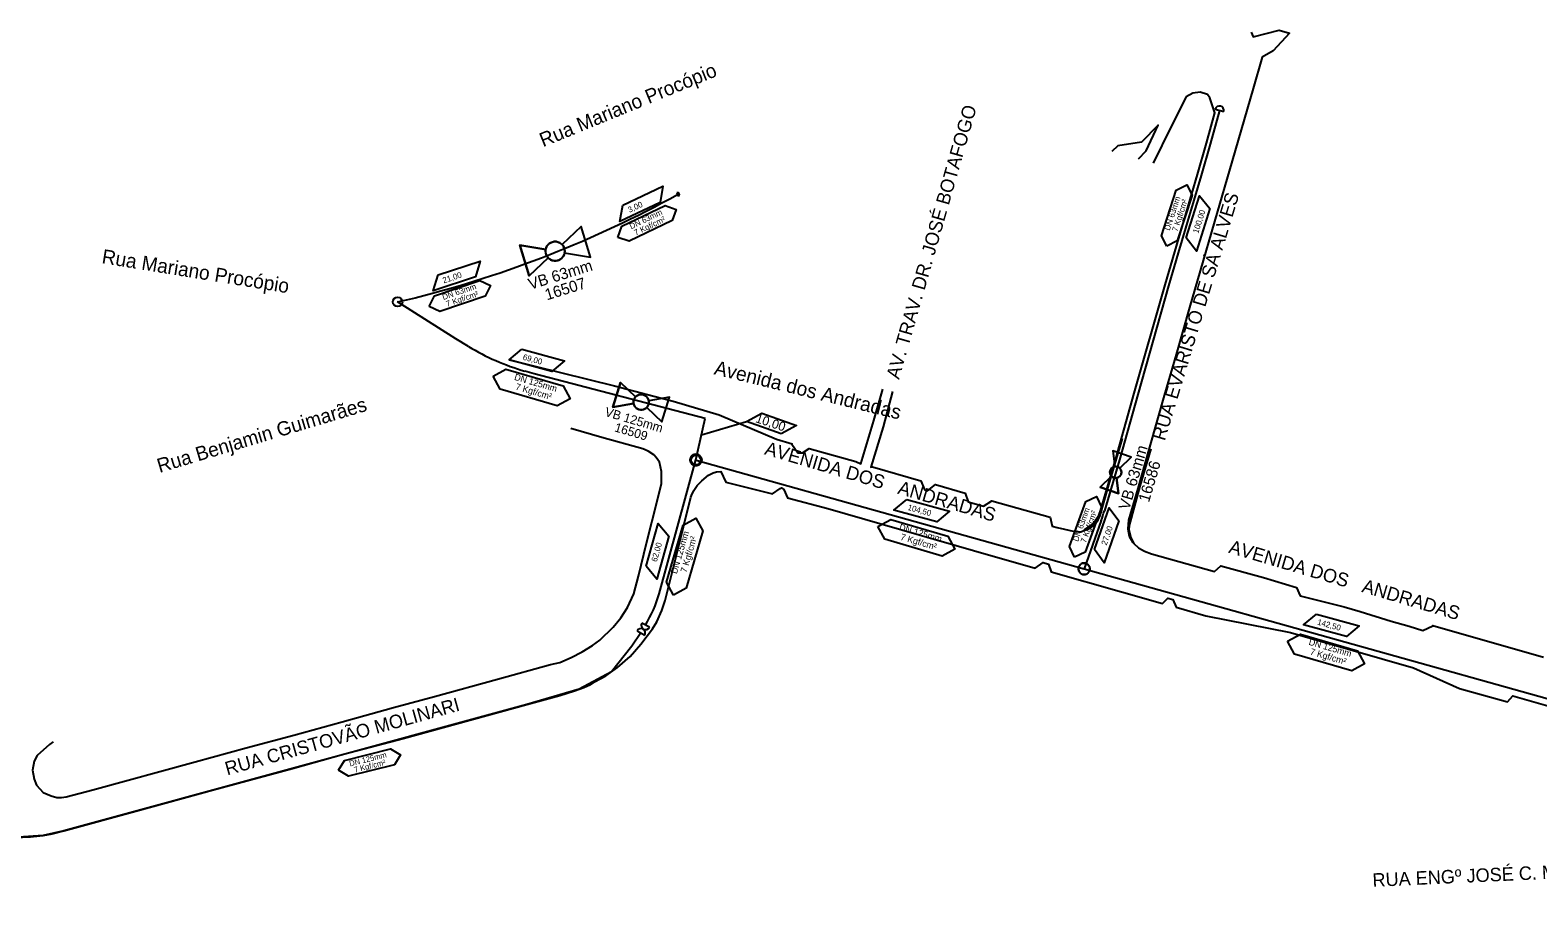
# Model space of a CAD drawing. Extents: x 656692 to 673945, y 7585994 to 7599066.
# Drawn here: x 667977 to 668779, y 7596748 to 7597212 of the extents above; entities that cross this region are included whole.
import ezdxf

# ---------------------------------------------------------------- set-up
doc = ezdxf.new("R2010")
doc.units = 0
for name, color, linetype in [('LEGENDA', 7, 'Continuous'), ('LOGRADOURO', 7, 'Continuous'), ('LOGRADOURO_TEXTO', 7, 'Continuous'), ('SIMBOLO', 7, 'Continuous'), ('TEXTO', 7, 'Continuous'), ('TEXTO NOME DE RUA', 7, 'Continuous'), ('TUBO_PEAD_GN_125', 7, 'Continuous'), ('TUBO_PEAD_GN_63', 7, 'Continuous'), ('VALVULA_PEAD_125', 7, 'Continuous'), ('VALVULA_PEAD_63', 7, 'Continuous')]:
    doc.layers.add(name, color=color, linetype=linetype)

# ---------------------------------------------------------------- blocks, each defined once
blk = doc.blocks.new('INTERLIGACAO_12')
at = {"layer": 'SIMBOLO'}
blk.add_circle((0, 0), 4.19, dxfattribs=at)
for start, end in [(0, 180), (180, 0)]:
    blk.add_arc((0, 0), 4.19, start, end, dxfattribs=at)
blk = doc.blocks.new('VALVULA_PEAD_DN_20')
at = {"layer": 'VALVULA_PEAD_63'}
for points in [[(-0.037, 0.019), (-0.14, 0.07), (-0.14, -0.07), (-0.037, -0.019)], [(-0.037, -0.019), (-0.14, -0.07), (-0.14, 0.07), (-0.037, 0.019)], [(0.037, -0.019), (0.14, -0.07), (0.14, 0.07), (0.037, 0.019)], [(0.037, -0.019), (0.14, -0.07), (0.14, 0.07), (0.037, 0.019)]]:
    blk.add_lwpolyline(points, dxfattribs=at)
blk.add_circle((0, 0), 0.0419, dxfattribs=at)
for start, end in [(90, 270), (153.4349, 206.5651), (270, 90), (333.4349, 26.5651)]:
    blk.add_arc((0, 0), 0.0419, start, end, dxfattribs=at)
blk = doc.blocks.new('VALVULA_PEAD_DN_9')
at = {"layer": 'VALVULA_PEAD_63'}
for points in [[(-1.14, 0.57), (-4.25, 2.13), (-4.25, -2.13), (-1.14, -0.57)], [(-1.14, -0.57), (-4.25, -2.13), (-4.25, 2.13), (-1.14, 0.57)], [(1.14, -0.57), (4.25, -2.13), (4.25, 2.13), (1.14, 0.57)], [(1.14, -0.57), (4.25, -2.13), (4.25, 2.13), (1.14, 0.57)]]:
    blk.add_lwpolyline(points, dxfattribs=at)
blk.add_circle((0, 0), 1.28, dxfattribs=at)
for start, end in [(90, 270), (153.4349, 206.5651), (270, 90), (0, 26.5651), (333.4349, 0)]:
    blk.add_arc((0, 0), 1.28, start, end, dxfattribs=at)

msp = doc.modelspace()

# ---------------------------------------------------------------- linework, layer by layer
at = {"layer": 'LEGENDA'}
for centre in [(668172.27, 7597067.58), (668172.27, 7597067.58), (668330.9, 7596983.47), (668330.9, 7596983.47)]:
    msp.add_circle(centre, 2.54, dxfattribs=at)
at = {"layer": 'LOGRADOURO'}
for points in [[(668626.08, 7597211.04), (668627.16, 7597208.64), (668640.96, 7597212.15), (668646.46, 7597210.47), (668637.9, 7597201.09), (668632.06, 7597197.78), (668627.21, 7597181.13), (668616.04, 7597142.63), (668606.69, 7597110.42), (668599.05, 7597084.04), (668593.36, 7597064.61), (668586.31, 7597039.61), (668579.97, 7597017.83), (668576.19, 7597004.62), (668571.76, 7596988.99), (668565.84, 7596968.34), (668560.92, 7596951.45), (668560.52, 7596946.77), (668561.35, 7596942.97), (668563.23, 7596939.55)], [(668537.37, 7596946.27), (668542.01, 7596949.23), (668545.45, 7596954.66), (668554.12, 7596984.06), (668563.99, 7597018.93), (668580.33, 7597076.63), (668585.47, 7597094.17), (668597.59, 7597135.42), (668602.35, 7597152.08), (668606.88, 7597168.2), (668604.21, 7597176.21), (668602.9, 7597177.91), (668598.97, 7597179.18), (668595.17, 7597178.64), (668591.6, 7597176.72), (668583.47, 7597160.51), (668573.97, 7597141.42)], [(668566.2, 7597143.64), (668570.23, 7597148.02), (668576.63, 7597161.67), (668567.87, 7597152.49), (668555.23, 7597150.54), (668552.01, 7597147.67)], [(668231.57, 7597036.76), (668287.62, 7597022.96), (668308.53, 7597017.47), (668318.87, 7597014.71), (668343.33, 7597007.51), (668373.67, 7596994.48), (668382.08, 7596992.01), (668381.89, 7596991.82), (668385.03, 7596987.27), (668387.5, 7596987.21), (668391.05, 7596989.56), (668415.9, 7596982.57), (668418.65, 7596981.34), (668425.47, 7597004.52), (668430.28, 7597021.14)], [(668435.45, 7597019.81), (668430.42, 7597001.01), (668423.99, 7596979.69), (668424.76, 7596979.82), (668450.43, 7596972.4), (668452.48, 7596967.81), (668454.09, 7596967.02), (668458.29, 7596970.36), (668474.03, 7596965.89), (668475.67, 7596961.26), (668483.8, 7596958.94), (668488.18, 7596961.75), (668519.21, 7596953.04), (668520.38, 7596948.3), (668522.97, 7596947.61), (668533.18, 7596945.22), (668535.98, 7596945.48), (668539.73, 7596946.86), (668541.44, 7596947.92), (668542.95, 7596949.2), (668544.84, 7596951.65), (668545.81, 7596953.84), (668550.46, 7596970.18), (668557.68, 7596994.91)], [(667989.12, 7596833.52), (667987.12, 7596832.04), (667980.56, 7596826.17), (667979.12, 7596823.3), (667978.23, 7596818.35), (667978.96, 7596813.58), (667980.3, 7596810.54), (667983.91, 7596806.5), (667988.03, 7596804.72), (667991.12, 7596803.9), (667993.61, 7596803.96), (667996.09, 7596804.3), (668010.31, 7596808.06), (668064.6, 7596822.88), (668091.83, 7596830.34), (668117.03, 7596837.13), (668142.76, 7596844.14), (668170.1, 7596851.74), (668191.97, 7596857.61), (668225.36, 7596866.83), (668253.67, 7596874.57), (668258.5, 7596875.77), (668264.58, 7596878.32), (668270.38, 7596881.48), (668275.85, 7596884.74), (668279.83, 7596887.57), (668286.87, 7596894.44), (668291.07, 7596899.43), (668294.53, 7596904.96), (668297.83, 7596912.33), (668300.42, 7596921.67), (668304.72, 7596939.27), (668310.45, 7596962.29), (668312.64, 7596970.93), (668312.62, 7596977.36), (668311.52, 7596982.25), (668309.76, 7596984.83), (668308.47, 7596986.17), (668305.49, 7596988.08), (668302.68, 7596989.33), (668280.96, 7596995.48), (668264.32, 7597000.28)], [(668572.76, 7596989.48), (668567.01, 7596969.51), (668561.22, 7596948.62), (668561.18, 7596946.18), (668562.19, 7596942.01), (668563.73, 7596939.1), (668566.25, 7596936.67), (668569.43, 7596934.93), (668573.14, 7596933.58), (668606.72, 7596924.12), (668610.05, 7596927.16), (668632.78, 7596921.02), (668650.19, 7596915.7), (668652.14, 7596911.14), (668675.68, 7596905.4), (668684.18, 7596902.92), (668700.57, 7596897.77), (668710.14, 7596895.03), (668717.43, 7596892.7), (668722.68, 7596895.27), (668722.66, 7596895.4), (668781.51, 7596878.51)], [(667964.45, 7596782.52), (667977.13, 7596783.01), (667983.77, 7596783.76), (667988.56, 7596784.6), (667994.84, 7596786.2), (668033.19, 7596796.69), (668074.33, 7596807.96), (668116.41, 7596819.36), (668143.54, 7596826.87), (668175.24, 7596835.33), (668240.99, 7596853.41), (668258.49, 7596858.21), (668266.4, 7596860.71), (668271.35, 7596862.5), (668274.43, 7596863.88), (668276.94, 7596865.35), (668282.96, 7596868.61), (668289.16, 7596872.98), (668295.86, 7596878.88), (668301.64, 7596885.47), (668307.84, 7596893.71), (668310.17, 7596897.41), (668312.76, 7596903.31), (668314.56, 7596908.7), (668320.49, 7596932.15), (668328.28, 7596963.75), (668328.88, 7596965.4), (668329.76, 7596967), (668329.88, 7596967.28), (668331.64, 7596969.95), (668334.06, 7596972.44), (668337.66, 7596975.35), (668340.05, 7596976.57), (668341.8, 7596977.13), (668344.08, 7596977.27), (668346.85, 7596971.74), (668371.62, 7596965.52), (668375.64, 7596968.25), (668376.45, 7596968.59), (668377.57, 7596967.73), (668379.52, 7596963.26), (668401.11, 7596957.66), (668478.52, 7596935.35), (668511.35, 7596925.92), (668515.55, 7596928.97), (668518.46, 7596927.96), (668519.85, 7596923.9), (668557.24, 7596913.32), (668578.93, 7596907.16), (668581.75, 7596910.03), (668584.49, 7596909.29), (668586.29, 7596905.23), (668601.97, 7596900.47), (668647.03, 7596891.63), (668712.39, 7596872.94), (668737, 7596861.85), (668762.42, 7596854.78), (668765.32, 7596857.97), (668788.84, 7596851.31)]]:
    msp.add_lwpolyline(points, dxfattribs=at)
at = {"layer": 'SIMBOLO'}
msp.add_line((668333.84, 7596996.9), (668357.79, 7597003.98), dxfattribs=at)
for points in [[(668581.23, 7597097.17), (668578.39, 7597102.74), (668586.28, 7597127.03), (668591.85, 7597129.87), (668594.69, 7597124.3), (668586.81, 7597100.01), (668581.23, 7597097.17)], [(668289.43, 7597101.87), (668291.5, 7597107.77), (668314.52, 7597118.84), (668320.42, 7597116.77), (668318.35, 7597110.87), (668295.34, 7597099.8), (668289.43, 7597101.87)], [(668189.12, 7597065.19), (668191.89, 7597070.8), (668216.07, 7597079), (668221.68, 7597076.23), (668218.91, 7597070.62), (668194.73, 7597062.42), (668189.12, 7597065.19)], [(668223.07, 7597027.99), (668229.87, 7597031.72), (668260.25, 7597022.83), (668263.97, 7597016.03), (668257.17, 7597012.3), (668226.79, 7597021.19), (668223.07, 7597027.99)], [(668532.29, 7596931.69), (668529.61, 7596937.35), (668538.22, 7596961.39), (668543.88, 7596964.07), (668546.55, 7596958.41), (668537.95, 7596934.37), (668532.29, 7596931.69)], [(668318.92, 7596911.62), (668315.2, 7596918.42), (668324.09, 7596948.79), (668330.89, 7596952.52), (668334.61, 7596945.71), (668325.72, 7596915.34), (668318.92, 7596911.62)], [(668427.7, 7596948.06), (668434.5, 7596951.78), (668464.87, 7596942.89), (668468.6, 7596936.09), (668461.8, 7596932.37), (668431.42, 7596941.25), (668427.7, 7596948.06)], [(668645.5, 7596887.03), (668652.3, 7596890.75), (668682.68, 7596881.86), (668686.4, 7596875.06), (668679.6, 7596871.34), (668649.22, 7596880.23), (668645.5, 7596887.03)], [(668140.91, 7596818.36), (668144.09, 7596823.66), (668168.59, 7596829.77), (668173.9, 7596826.59), (668170.71, 7596821.28), (668146.21, 7596815.17), (668140.91, 7596818.36)]]:
    msp.add_lwpolyline(points, dxfattribs=at)
msp.add_lwpolyline([(668376.25, 7596997.37), (668357.79, 7597003.98), (668365.87, 7597008.4), (668384.34, 7597001.79)], close=True, dxfattribs=at)
at = {"layer": 'TEXTO'}
for points in [[(668292.05, 7597119.11), (668313.33, 7597129.09), (668311.92, 7597120.44), (668290.51, 7597110.4), (668292.05, 7597119.11)], [(668591.63, 7597101.66), (668598.72, 7597124.07), (668604.13, 7597117.17), (668596.99, 7597094.62), (668591.63, 7597101.66)], [(668193.8, 7597081.99), (668216.14, 7597089.32), (668213.69, 7597080.91), (668191.22, 7597073.53), (668193.8, 7597081.99)], [(668238.4, 7597042.38), (668261.06, 7597036.14), (668254.37, 7597030.48), (668231.57, 7597036.76), (668238.4, 7597042.38)], [(668443.03, 7596962.44), (668465.69, 7596956.2), (668459, 7596950.54), (668436.2, 7596956.82), (668443.03, 7596962.44)], [(668542.82, 7596935.87), (668550.57, 7596958.06), (668555.77, 7596951), (668547.96, 7596928.68), (668542.82, 7596935.87)], [(668304.53, 7596926.95), (668310.77, 7596949.61), (668316.43, 7596942.92), (668310.16, 7596920.12), (668304.53, 7596926.95)], [(668660.83, 7596901.41), (668683.49, 7596895.18), (668676.8, 7596889.52), (668654, 7596895.79), (668660.83, 7596901.41)]]:
    msp.add_lwpolyline(points, dxfattribs=at)
at = {"layer": 'TUBO_PEAD_GN_125'}
for p, q in [((668330.9, 7596983.47), (668335.75, 7597005.62)), ((668331.12, 7596983.38), (668805.83, 7596850.22)), ((668306.21, 7596894.45), (668302.1, 7596896.67)), ((668299.63, 7596892.5), (668303.74, 7596890.28))]:
    msp.add_line(p, q, dxfattribs=at)
for points in [[(668209.95, 7597043.89), (668203.33, 7597047.89), (668172.27, 7597067.58)], [(668335.75, 7597005.62), (668244.84, 7597029.29), (668239.91, 7597030.73)], [(668311.42, 7596912.27), (668330.9, 7596983.47), (668330.9, 7596983.47)], [(668301.62, 7596891.42), (668296.79, 7596884.36), (668286.06, 7596870.79), (668268.87, 7596861.6), (668240.99, 7596853.41), (667994.84, 7596786.2), (667983.77, 7596783.76), (667970.79, 7596782.76), (667952.83, 7596783.61), (667909.51, 7596794.38), (667905.28, 7596794.54), (667902.59, 7596794.01), (667893.41, 7596789.27), (667867.11, 7596772.34), (667851.19, 7596757.31), (667844.21, 7596747.84), (667786.16, 7596779.27)]]:
    msp.add_lwpolyline(points, dxfattribs=at)
for centre, radius, start, end in [((668275.16, 7597151.7), 126, 238.82978, 253.75404), ((668240.45, 7596933.53), 74.09, 329.20041, 343.32059), ((668304.16, 7596895.56), 2.34, 151.64019, 331.49184), ((668301.68, 7596891.39), 2.34, 331.64019, 151.49184)]:
    msp.add_arc(centre, radius, start, end, dxfattribs=at)
at = {"layer": 'TUBO_PEAD_GN_63'}
for p, q in [((668607.04, 7597170.02), (668611.58, 7597168.88)), ((668320.72, 7597125.64), (668321.59, 7597123.68)), ((668172.27, 7597067.58), (668181.72, 7597069.75)), ((668546.39, 7596951.18), (668537.38, 7596925.54))]:
    msp.add_line(p, q, dxfattribs=at)
msp.add_lwpolyline([(668609.31, 7597169.45), (668604.28, 7597151.54), (668599.52, 7597134.86), (668587.39, 7597093.61), (668582.26, 7597076.08), (668565.92, 7597018.38), (668556.05, 7596983.51), (668548.08, 7596956.49)], dxfattribs=at)
for centre, radius, start, end in [((668609.31, 7597169.45), 2.34, 346.00511, 165.85676), ((668036.4, 7597643.24), 591.61, 284.219, 298.77118), ((668321.02, 7597124.6), 1.08, 301.68085, 106.02766), ((668477.83, 7596975.92), 72.88, 340.15217, 344.53772)]:
    msp.add_arc(centre, radius, start, end, dxfattribs=at)

# ---------------------------------------------------------------- block references
at = {"layer": 'SIMBOLO', "xscale": 0.7324163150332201, "yscale": 0.7324163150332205, "rotation": 166.3322212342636}
for p in [(668330.9, 7596983.47), (668537.38, 7596925.54)]:
    msp.add_blockref('INTERLIGACAO_12', p, dxfattribs=at)
at = {"layer": 'VALVULA_PEAD_125', "xscale": 3.1999999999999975, "yscale": 3.1999999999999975, "rotation": -16.862842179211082}
msp.add_blockref('VALVULA_PEAD_DN_9', (668301.81, 7597014.22), dxfattribs=at)
at = {"layer": 'VALVULA_PEAD_63'}
for name, p, xscale, yscale, rotation in [('VALVULA_PEAD_DN_9', (668256.06, 7597094.52), 3.9999999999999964, 3.9999999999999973, 16.92157531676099), ('VALVULA_PEAD_DN_20', (668554.11, 7596976.93), 73.24163150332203, 73.24163150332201, 70.81511651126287)]:
    msp.add_blockref(name, p, dxfattribs=dict(at, xscale=xscale, yscale=yscale, rotation=rotation))

# ---------------------------------------------------------------- texts
for s, height, rotation, p in [('VB 63mm', 6, 17.2901, (668242.85, 7597073.99)), ('16507', 6, 17.2901, (668251.67, 7597068.36)), ('VB 125mm', 4.8, 343.50568, (668282.11, 7597006.98)), ('16509', 4.8, 343.50568, (668287.26, 7596998.78)), ('VB 63mm', 6, 73.55647, (668561.22, 7596956.48)), ('16586', 6, 73.55647, (668571.8, 7596960.59))]:
    msp.add_text(s, height=height, rotation=rotation).set_placement(p)
at = {"layer": 'LOGRADOURO_TEXTO'}
for s, rotation, p in [('AV. TRAV. DR. JOSÉ BOTAFOGO', 74.08128, (668438.91, 7597026.03)), ('RUA EVARISTO DE SÁ ALVES', 73.17654, (668580.17, 7596993.29)), ('AVENIDA DOS   ANDRADAS', 343.57981, (668366.95, 7596986.53)), ('AVENIDA DOS   ANDRADAS', 343.57981, (668613.74, 7596934.2)), ('RUA CRISTOVÃO MOLINARI', 15.57635, (668081.67, 7596815.62)), ('RUA ENGº JOSÉ C. MORAIS SARMENTO ', 2.59307, (668690.81, 7596756.34))]:
    msp.add_text(s, height=7.2, rotation=rotation, dxfattribs=at).set_placement(p)
at = {"layer": 'TEXTO'}
for s, height, rotation, p in [('3,00', 3.113, 25.11359, (668295.6, 7597114.92)), ('DN 63mm', 3.113, 72.01829, (668582.81, 7597105.29)), ('7 Kgf/cm²', 3.113, 72.01829, (668586.96, 7597104.71)), ('DN 63mm', 3.113, 25.68449, (668296.51, 7597106.13)), ('7 Kgf/cm²', 3.113, 25.68449, (668298.95, 7597102.73)), ('100,00', 3.113, 72.4409, (668597.99, 7597103.79)), ('21,00', 3.113, 18.16277, (668196.82, 7597077.4)), ('DN 63mm', 3.113, 18.73367, (668196.66, 7597068.56)), ('7 Kgf/cm²', 3.113, 18.73367, (668198.67, 7597064.89)), ('69,00', 3.113, 344.60781, (668238.63, 7597036.87)), ('DN 125mm', 3.459, 343.69142, (668234.06, 7597026.17)), ('7 Kgf/cm²', 3.459, 343.69142, (668234.71, 7597020.99)), ('10,00', 4.838, 341.62015, (668362.23, 7597003.66)), ('104,50', 3.113, 344.60781, (668443.26, 7596956.93)), ('DN 63mm', 3.113, 70.30493, (668534.11, 7596939.76)), ('7 Kgf/cm²', 3.113, 70.30493, (668538.24, 7596939.05)), ('DN 125mm', 3.459, 73.69142, (668320.74, 7596922.61)), ('DN 125mm', 3.459, 343.69142, (668438.69, 7596946.23)), ('7 Kgf/cm²', 3.459, 343.69142, (668439.34, 7596941.05)), ('27,00', 3.113, 70.72754, (668549.24, 7596937.81)), ('62,00', 3.113, 74.60781, (668310.12, 7596929.02)), ('7 Kgf/cm²', 3.459, 73.69142, (668325.92, 7596923.26)), ('142,50', 3.113, 344.60781, (668661.06, 7596895.91)), ('DN 125mm', 3.459, 343.69142, (668656.49, 7596885.21)), ('7 Kgf/cm²', 3.459, 343.69142, (668657.14, 7596880.03)), ('DN 125mm', 3, 14.00573, (668147, 7596820.39)), ('7 Kgf/cm²', 3, 14.00573, (668149.5, 7596817.1))]:
    msp.add_text(s, height=height, rotation=rotation, dxfattribs=at).set_placement(p)
at = {"layer": 'TEXTO NOME DE RUA'}
for s, rotation, p in [('Rua Mariano Procópio', 22.27128, (668249.64, 7597149.82)), ('Rua Mariano Procópio', 350.81478, (668014.67, 7597088.21)), ('Avenida dos Andradas', 346.2635, (668340.15, 7597029.11)), ('Rua Benjamin Guimarães', 16.69401, (668045.71, 7596976.54))]:
    msp.add_text(s, height=7.56, rotation=rotation, dxfattribs=at).set_placement(p)

doc.saveas('drawing.dxf')
